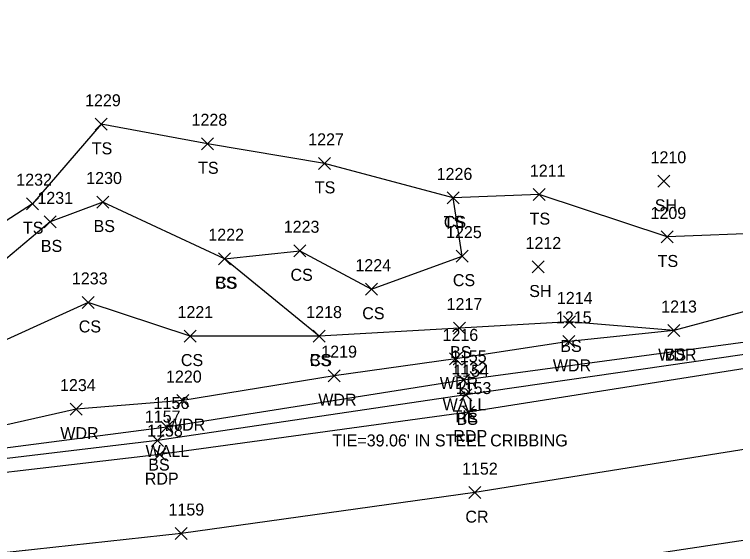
# Model space of a CAD drawing. Extents: x 1502119 to 1504100, y 606168 to 606406.
# Drawn here: x 1503736.1 to 1503856.3, y 606294.7 to 606383 of the extents above; entities that cross this region are included whole.
import ezdxf

# ---------------------------------------------------------------- set-up
doc = ezdxf.new("R2010")
doc.units = 0
for name, color, linetype in [('C_A', 7, 'Continuous'), ('C_C', 7, 'Continuous'), ('C_I', 7, 'Continuous'), ('CBP', 7, 'Continuous'), ('L_A', 7, 'Continuous'), ('L_I', 7, 'Continuous'), ('L_TIC', 7, 'Continuous'), ('LAWA', 7, 'Continuous'), ('LELB', 7, 'Continuous'), ('LW', 7, 'Continuous'), ('P_A', 7, 'Continuous'), ('P_I', 7, 'Continuous'), ('P_TIC', 7, 'Continuous'), ('PET', 7, 'Continuous'), ('PRC', 7, 'Continuous')]:
    doc.layers.add(name, color=color, linetype=linetype)

msp = doc.modelspace()

# ---------------------------------------------------------------- linework, layer by layer
at = {"layer": 'CBP'}
for radius in [0.625, 0.0833]:
    msp.add_circle((1503811, 606320.04), radius, dxfattribs=at)
at = {"layer": 'L_TIC'}
for points in [[(1503749.54, 606363.68), (1503751.54, 606365.68)], [(1503751.54, 606363.68), (1503749.54, 606365.68)], [(1503767.27, 606360.44), (1503769.27, 606362.44)], [(1503769.27, 606360.44), (1503767.27, 606362.44)], [(1503786.72, 606357.18), (1503788.72, 606359.18)], [(1503788.72, 606357.18), (1503786.72, 606359.18)], [(1503843.31, 606354.19), (1503845.31, 606356.19)], [(1503845.31, 606354.19), (1503843.31, 606356.19)], [(1503822.53, 606351.97), (1503824.53, 606353.97)], [(1503824.53, 606351.97), (1503822.53, 606353.97)], [(1503738.07, 606350.46), (1503740.07, 606352.46)], [(1503740.07, 606350.46), (1503738.07, 606352.46)], [(1503749.81, 606350.74), (1503751.81, 606352.74)], [(1503751.81, 606350.74), (1503749.81, 606352.74)], [(1503808.18, 606351.42), (1503810.18, 606353.42)], [(1503810.18, 606351.42), (1503808.18, 606353.42)], [(1503808.18, 606351.42), (1503810.18, 606353.42)], [(1503810.18, 606351.42), (1503808.18, 606353.42)], [(1503741.02, 606347.43), (1503743.02, 606349.43)], [(1503743.02, 606347.43), (1503741.02, 606349.43)], [(1503843.87, 606344.92), (1503845.87, 606346.92)], [(1503845.87, 606344.92), (1503843.87, 606346.92)], [(1503782.64, 606342.62), (1503784.64, 606344.62)], [(1503784.64, 606342.62), (1503782.64, 606344.62)], [(1503770.08, 606341.3), (1503772.08, 606343.3)], [(1503772.08, 606341.3), (1503770.08, 606343.3)], [(1503770.08, 606341.3), (1503772.08, 606343.3)], [(1503772.08, 606341.3), (1503770.08, 606343.3)], [(1503809.7, 606341.73), (1503811.7, 606343.73)], [(1503811.7, 606341.73), (1503809.7, 606343.73)], [(1503822.38, 606339.92), (1503824.38, 606341.92)], [(1503824.38, 606339.92), (1503822.38, 606341.92)], [(1503794.59, 606336.22), (1503796.59, 606338.22)], [(1503796.59, 606336.22), (1503794.59, 606338.22)], [(1503747.33, 606334.02), (1503749.33, 606336.02)], [(1503749.33, 606334.02), (1503747.33, 606336.02)], [(1503827.6, 606330.77), (1503829.6, 606332.77)], [(1503829.6, 606330.77), (1503827.6, 606332.77)], [(1503809.23, 606329.74), (1503811.23, 606331.74)], [(1503811.23, 606329.74), (1503809.23, 606331.74)], [(1503845, 606329.34), (1503847, 606331.34)], [(1503847, 606329.34), (1503845, 606331.34)], [(1503845, 606329.34), (1503847, 606331.34)], [(1503847, 606329.34), (1503845, 606331.34)], [(1503764.37, 606328.42), (1503766.37, 606330.42)], [(1503766.37, 606328.42), (1503764.37, 606330.42)], [(1503785.83, 606328.41), (1503787.83, 606330.41)], [(1503787.83, 606328.41), (1503785.83, 606330.41)], [(1503785.83, 606328.41), (1503787.83, 606330.41)], [(1503787.83, 606328.41), (1503785.83, 606330.41)], [(1503827.45, 606327.53), (1503829.45, 606329.53)], [(1503829.45, 606327.53), (1503827.45, 606329.53)], [(1503808.6, 606324.61), (1503810.6, 606326.61)], [(1503810.6, 606324.61), (1503808.6, 606326.61)], [(1503788.35, 606321.82), (1503790.35, 606323.82)], [(1503790.35, 606321.82), (1503788.35, 606323.82)], [(1503809.94, 606321.05), (1503811.94, 606323.05)], [(1503811.94, 606321.05), (1503809.94, 606323.05)], [(1503810.33, 606318.63), (1503812.33, 606320.63)], [(1503812.33, 606318.63), (1503810.33, 606320.63)], [(1503763.11, 606317.67), (1503765.11, 606319.67)], [(1503765.11, 606317.67), (1503763.11, 606319.67)], [(1503745.35, 606316.25), (1503747.35, 606318.25)], [(1503747.35, 606316.25), (1503745.35, 606318.25)], [(1503760.44, 606313.27), (1503762.44, 606315.27)], [(1503762.44, 606313.27), (1503760.44, 606315.27)], [(1503758.93, 606311.02), (1503760.93, 606313.02)], [(1503760.93, 606311.02), (1503758.93, 606313.02)]]:
    msp.add_lwpolyline(points, dxfattribs=at)
at = {"layer": 'LAWA'}
msp.add_lwpolyline([(1503990.71, 606382.98), (1503966.9, 606374.16), (1503949.79, 606353.75), (1503942.92, 606352.55), (1503916.64, 606344.82), (1503911.63, 606340.49), (1503904.12, 606338.88), (1503887.71, 606335.33), (1503868.8, 606333.95), (1503861.91, 606334.62), (1503846, 606330.34), (1503828.45, 606328.53), (1503809.6, 606325.61), (1503789.35, 606322.82), (1503764.11, 606318.67), (1503746.35, 606317.25), (1503727.35, 606312.95), (1503709.14, 606312.53), (1503674.87, 606310.32), (1503655.25, 606308.46), (1503623.87, 606310.46), (1503602.45, 606314.46)], dxfattribs=at)
at = {"layer": 'LELB'}
for points in [[(1503923.46, 606369.4), (1503921.54, 606359.43), (1503912.25, 606356.2), (1503893.52, 606356.21), (1503867.3, 606351.42), (1503862.16, 606346.63), (1503844.87, 606345.92), (1503823.53, 606352.97), (1503809.18, 606352.42), (1503787.72, 606358.18), (1503768.27, 606361.44), (1503750.54, 606364.68), (1503739.07, 606351.46), (1503723.82, 606341.62), (1503705.03, 606342.87), (1503687.78, 606335.89), (1503674.36, 606336.73), (1503654.48, 606335.34), (1503625.89, 606329.25), (1503604.28, 606329.18)], [(1503942.92, 606352.55), (1503928.1, 606340.43), (1503910.71, 606333.69), (1503861.57, 606326.92), (1503811.33, 606319.63), (1503759.93, 606312.02), (1503711.14, 606306.21), (1503662.13, 606303.9), (1503623.99, 606305.38), (1503602.03, 606307.61), (1503601.52, 606307.57), (1503602.45, 606314.46)], [(1503771.08, 606342.3), (1503783.64, 606343.62), (1503795.59, 606337.22), (1503810.7, 606342.73), (1503809.18, 606352.42)], [(1503846, 606330.34), (1503828.6, 606331.77), (1503810.23, 606330.74), (1503786.83, 606329.41), (1503771.08, 606342.3), (1503750.81, 606351.74), (1503742.02, 606348.43), (1503727.18, 606336.01), (1503706.81, 606334.09), (1503689.48, 606323.52), (1503674.57, 606324.03), (1503655.14, 606322.12), (1503623.35, 606316.81), (1503603, 606316.64)], [(1503786.83, 606329.41), (1503765.37, 606329.42), (1503748.33, 606335.02), (1503728.63, 606326.07), (1503708.3, 606327.73), (1503689.48, 606323.52)]]:
    msp.add_lwpolyline(points, dxfattribs=at)
at = {"layer": 'LW'}
msp.add_lwpolyline([(1503910.46, 606334.58), (1503860.8, 606328.79), (1503810.94, 606322.05), (1503761.44, 606314.27), (1503711.84, 606307.81), (1503661.97, 606305.03), (1503624.1, 606306.33), (1503602.1, 606309.62), (1503602.45, 606314.46)], dxfattribs=at)
at = {"layer": 'P_TIC'}
for points in [[(1503810.74, 606315.76), (1503812.74, 606317.76)], [(1503812.74, 606315.76), (1503810.74, 606317.76)], [(1503759.3, 606308.68), (1503761.3, 606310.68)], [(1503761.3, 606308.68), (1503759.3, 606310.68)], [(1503811.8, 606302.34), (1503813.8, 606304.34)], [(1503813.8, 606302.34), (1503811.8, 606304.34)], [(1503762.88, 606295.53), (1503764.88, 606297.53)], [(1503764.88, 606295.53), (1503762.88, 606297.53)]]:
    msp.add_lwpolyline(points, dxfattribs=at)
at = {"layer": 'PET'}
for points in [[(1504085.41, 606349.16), (1504052.4, 606348.69), (1503999.05, 606344.18), (1503952.76, 606337.92), (1503910.76, 606332.19), (1503862.06, 606324.66), (1503811.74, 606316.76), (1503760.3, 606309.68), (1503710.83, 606303.94), (1503662.2, 606301.66), (1503623.65, 606303.36), (1503601.52, 606305.18)], [(1504084.52, 606320.63), (1504050.65, 606320.45), (1504000.43, 606315.8), (1503956.16, 606310.12), (1503915.05, 606304.21), (1503867.85, 606296.91), (1503814.4, 606288.86), (1503766.38, 606281.21), (1503714.75, 606276.43), (1503655.34, 606274.1), (1503622.19, 606275.72), (1503601.58, 606277.52)]]:
    msp.add_lwpolyline(points, dxfattribs=at)
at = {"layer": 'PRC'}
msp.add_lwpolyline([(1504085.68, 606335.47), (1504051.53, 606335.36), (1503999.5, 606331.04), (1503953.49, 606324.86), (1503912.24, 606318.81), (1503865.3, 606311.74), (1503812.8, 606303.34), (1503763.88, 606296.53), (1503711.85, 606290.88), (1503656.36, 606289.42), (1503622.63, 606290.92), (1503602.08, 606292.63)], dxfattribs=at)

# ---------------------------------------------------------------- texts
at = {"layer": 'C_A'}
msp.add_text('TIE', height=2, dxfattribs=at).set_placement((1503809.08, 606315.04))
at = {"layer": 'C_C'}
msp.add_text("TIE=39.06' IN STEEL CRIBBING", height=2, dxfattribs=at).set_placement((1503789.06, 606311.04))
at = {"layer": 'C_I'}
msp.add_text('1132', height=2, dxfattribs=at).set_placement((1503808.88, 606323.04))
at = {"layer": 'L_A'}
for s, p in [('TS', (1503748.95, 606359.68)), ('TS', (1503766.68, 606356.44)), ('TS', (1503786.13, 606353.18)), ('SH', (1503842.8, 606350.19)), ('TS', (1503807.59, 606347.42)), ('CS', (1503807.63, 606347.42)), ('TS', (1503821.94, 606347.97)), ('TS', (1503737.48, 606346.46)), ('BS', (1503749.25, 606346.74)), ('BS', (1503740.46, 606343.43)), ('TS', (1503843.28, 606340.92)), ('CS', (1503782.08, 606338.62)), ('CS', (1503769.52, 606337.3)), ('BS', (1503769.52, 606337.3)), ('CS', (1503809.14, 606337.73)), ('SH', (1503821.87, 606335.92)), ('CS', (1503794.04, 606332.22)), ('CS', (1503746.78, 606330.02)), ('BS', (1503827.05, 606326.77)), ('BS', (1503808.67, 606325.74)), ('WDR', (1503843.36, 606325.34)), ('BS', (1503844.44, 606325.34)), ('CS', (1503763.81, 606324.42)), ('CS', (1503785.27, 606324.41)), ('BS', (1503785.27, 606324.41)), ('WDR', (1503825.81, 606323.53)), ('WDR', (1503806.96, 606320.61)), ('WDR', (1503786.71, 606317.82)), ('WALL', (1503807.43, 606317.05)), ('BS', (1503809.77, 606314.63)), ('WDR', (1503761.48, 606313.67)), ('WDR', (1503743.71, 606312.25)), ('WALL', (1503757.92, 606309.27)), ('BS', (1503758.37, 606307.02))]:
    msp.add_text(s, height=2, dxfattribs=at).set_placement(p)
at = {"layer": 'L_I'}
for s, p in [('1229', (1503747.84, 606367.68)), ('1228', (1503765.58, 606364.44)), ('1227', (1503785.03, 606361.18)), ('1210', (1503842.09, 606358.19)), ('1226', (1503806.44, 606355.42)), ('1226', (1503806.44, 606355.42)), ('1211', (1503821.97, 606355.97)), ('1232', (1503736.37, 606354.46)), ('1230', (1503748.03, 606354.74)), ('1231', (1503739.89, 606351.43)), ('1209', (1503842.09, 606348.92)), ('1223', (1503780.95, 606346.62)), ('1225', (1503808.01, 606345.73)), ('1222', (1503768.38, 606345.3)), ('1222', (1503768.38, 606345.3)), ('1212', (1503821.25, 606343.92)), ('1224', (1503792.9, 606340.22)), ('1233', (1503745.64, 606338.02)), ('1214', (1503826.48, 606334.77)), ('1217', (1503808.1, 606333.74)), ('1221', (1503763.24, 606332.42)), ('1218', (1503784.7, 606332.41)), ('1218', (1503784.7, 606332.41)), ('1213', (1503843.87, 606333.34)), ('1213', (1503843.87, 606333.34)), ('1215', (1503826.32, 606331.53)), ('1216', (1503807.42, 606328.61)), ('1219', (1503787.21, 606325.82)), ('1155', (1503808.82, 606325.05)), ('1220', (1503761.33, 606321.67)), ('1154', (1503809.2, 606322.63)), ('1234', (1503743.66, 606320.25)), ('1156', (1503759.26, 606317.27)), ('1157', (1503757.8, 606315.02))]:
    msp.add_text(s, height=2, dxfattribs=at).set_placement(p)
at = {"layer": 'P_A'}
for s, p in [('RDP', (1503809.22, 606311.76)), ('RDP', (1503757.79, 606304.68)), ('CR', (1503811.23, 606298.34))]:
    msp.add_text(s, height=2, dxfattribs=at).set_placement(p)
at = {"layer": 'P_I'}
for s, p in [('1153', (1503809.61, 606319.76)), ('1158', (1503758.18, 606312.68)), ('1152', (1503810.67, 606306.34)), ('1159', (1503761.74, 606299.53))]:
    msp.add_text(s, height=2, dxfattribs=at).set_placement(p)

doc.saveas('drawing.dxf')
